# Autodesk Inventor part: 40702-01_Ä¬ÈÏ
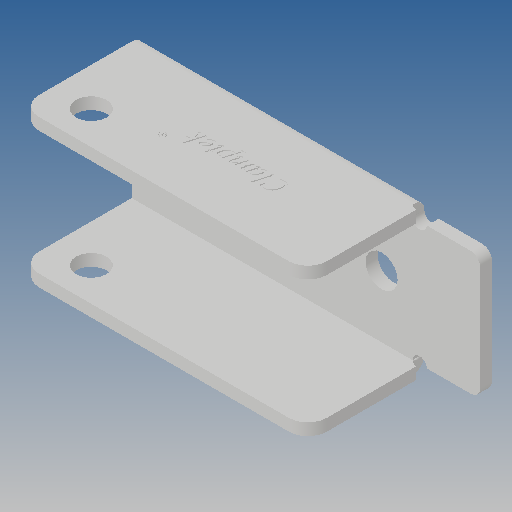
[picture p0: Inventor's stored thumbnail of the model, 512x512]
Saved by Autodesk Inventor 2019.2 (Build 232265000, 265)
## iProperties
Created: 2010-06
Part Number: 40702-01_Ä¬ÈÏ
Material: Ogólny
Document SubType Name: Modeling
Designer: CADENGINEERING4
Density: 1 g/cm^3
Appearance: Domyślna
Author: CADENGINEERING4
Revision Number: ÈÎºÎ
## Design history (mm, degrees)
feature "NONE"
node "Bryła1"
